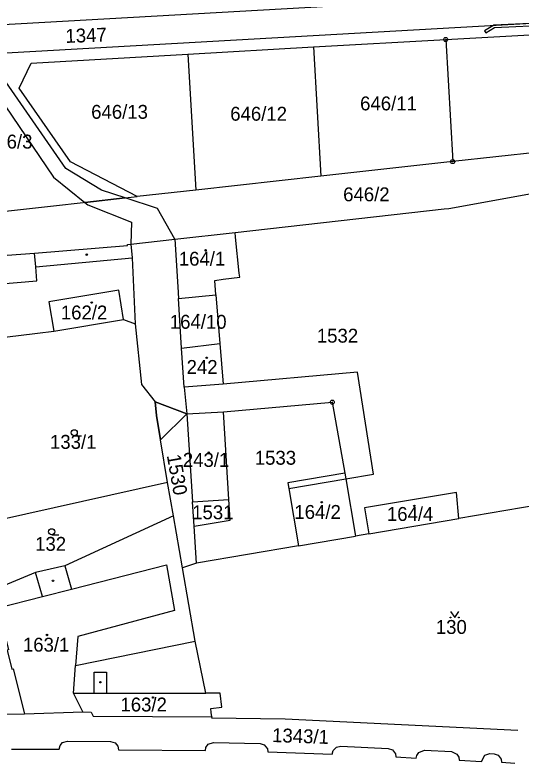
# Model space of a CAD drawing. Extents: x -537341 to -532984, y -1143469 to -1141314.
# Drawn here: x -533659.4 to -533535.5, y -1143096.3 to -1142913.3 of the extents above; entities that cross this region are included whole.
import ezdxf

# ---------------------------------------------------------------- set-up
doc = ezdxf.new("R2010")
doc.units = 0
for name, color, linetype in [('Hranice parcel', 7, 'Continuous'), ('parcelní_č_2000', 7, 'Continuous'), ('Vnitřní kresba', 7, 'Continuous'), ('Věcná břemena k části', 7, 'Continuous'), ('Značky bodu BP', 7, 'Continuous'), ('Značky budov', 7, 'Continuous'), ('Značky kultur', 7, 'Continuous')]:
    doc.layers.add(name, color=color, linetype=linetype)

msp = doc.modelspace()

# ---------------------------------------------------------------- linework, layer by layer
at = {"layer": 'Hranice parcel'}
for p, q in [((-533666.46, -1142915.84), (-533560.9, -1142909.85)), ((-533586.32, -1142921.09), (-533553.91, -1142919.27)), ((-533553.91, -1142919.27), (-533552.21, -1142949.14)), ((-533617.08, -1142922.83), (-533586.32, -1142921.09)), ((-533586.32, -1142921.09), (-533584.51, -1142952.72)), ((-533617.08, -1142922.83), (-533615.15, -1142956.13)), ((-533524.03, -1142946.01), (-533552.21, -1142949.14)), ((-533552.21, -1142949.14), (-533584.51, -1142952.72)), ((-533584.51, -1142952.72), (-533615.15, -1142956.13)), ((-533615.15, -1142956.13), (-533629.48, -1142957.72)), ((-533663.27, -1142961.47), (-533629.48, -1142957.72)), ((-533620.27, -1142968.15), (-533605.47, -1142966.49)), ((-533605.4, -1142967.65), (-533605.47, -1142966.49)), ((-533631.01, -1142969.31), (-533620.27, -1142968.15)), ((-533619.37, -1142982.64), (-533610.2, -1142981.72)), ((-533610.2, -1142981.72), (-533609.24, -1142993.64)), ((-533618.62, -1142994.79), (-533619.37, -1142982.64)), ((-533618.62, -1142994.79), (-533609.24, -1142993.64)), ((-533625.09, -1143007.91), (-533617.32, -1143010.84)), ((-533617.32, -1143010.84), (-533608.34, -1143010.37)), ((-533617.32, -1143010.84), (-533615.91, -1143032.37)), ((-533607.06, -1143031.82), (-533608.34, -1143010.37)), ((-533622.05, -1143027.66), (-533675.98, -1143039.7)), ((-533620.62, -1143035.85), (-533622.05, -1143027.66)), ((-533615.91, -1143032.37), (-533607.06, -1143031.82)), ((-533615.52, -1143038.34), (-533615.91, -1143032.37)), ((-533618.42, -1143048.52), (-533620.62, -1143035.85)), ((-533572.72, -1143040.23), (-533550.7, -1143036.5)), ((-533614.93, -1143047.39), (-533615.52, -1143038.34)), ((-533589.98, -1143043.16), (-533576.01, -1143040.79)), ((-533572.72, -1143040.23), (-533576.01, -1143040.79)), ((-533589.98, -1143043.16), (-533614.93, -1143047.39)), ((-533614.93, -1143047.39), (-533618.42, -1143048.52)), ((-533615.28, -1143066.53), (-533618.42, -1143048.52)), ((-533668.44, -1143084.49), (-533657.13, -1143084.25)), ((-533657.13, -1143084.25), (-533642.84, -1143083.81))]:
    msp.add_line(p, q, dxfattribs=at)
for points in [[(-533521.33, -1142914.7), (-533670.28, -1142923.14)], [(-533553.91, -1142919.27), (-533521.57, -1142917.45)], [(-533629.48, -1142957.72), (-533645.85, -1142949.18), (-533658.42, -1142931.2), (-533655.43, -1142925.03), (-533617.08, -1142922.83)], [(-533605.47, -1142966.49), (-533554.28, -1142960.73), (-533553.19, -1142960.59), (-533524.84, -1142955.48)], [(-533604.37, -1142977.44), (-533604.54, -1142976.41), (-533605.4, -1142967.65)], [(-533661.32, -1142972.07), (-533654.63, -1142971.54), (-533631.89, -1142969.71), (-533631.9, -1142969.41), (-533631.01, -1142969.31)], [(-533631.01, -1142969.31), (-533630.69, -1142972.7), (-533629.95, -1142988.83)], [(-533620.27, -1142968.15), (-533619.55, -1142979.78), (-533619.37, -1142982.64)], [(-533610.2, -1142981.72), (-533610.48, -1142978.27), (-533608.4, -1142977.92), (-533604.37, -1142977.44)], [(-533673.99, -1142993.57), (-533649.93, -1142990.6), (-533632.85, -1142987.8), (-533629.95, -1142988.83)], [(-533629.95, -1142988.83), (-533628.4, -1143003.7), (-533625.09, -1143007.91)], [(-533609.24, -1142993.64), (-533608.43, -1143003.59), (-533617.99, -1143004.35), (-533618.62, -1142994.79)], [(-533622.05, -1143027.66), (-533623.8, -1143017.22), (-533624.79, -1143011.27), (-533625.09, -1143007.91)], [(-533608.34, -1143010.37), (-533581.71, -1143008.01), (-533578.62, -1143025.41)], [(-533578.62, -1143025.41), (-533592.59, -1143027.78), (-533592.36, -1143029.15), (-533589.98, -1143043.16)], [(-533578.62, -1143025.41), (-533578.38, -1143026.79), (-533576.01, -1143040.79)], [(-533615.52, -1143038.34), (-533606.75, -1143036.87), (-533607.06, -1143031.82)], [(-533550.7, -1143036.5), (-533551.28, -1143030.12), (-533573.78, -1143033.88), (-533572.72, -1143040.23)], [(-533531.53, -1143033.25), (-533550.7, -1143036.5)], [(-533620.62, -1143035.85), (-533647.23, -1143048.1), (-533654.4, -1143049.71), (-533672.54, -1143057.19)], [(-533671.93, -1143060.22), (-533663.59, -1143058.34), (-533661.02, -1143068.63), (-533661.31, -1143068.71), (-533660.16, -1143073.31), (-533659.87, -1143073.24), (-533657.13, -1143084.25)], [(-533642.84, -1143083.81), (-533645.07, -1143079.19), (-533644.58, -1143072.41), (-533615.28, -1143066.53)], [(-533611.24, -1143085.02), (-533611.36, -1143083.92), (-533611.47, -1143082.94), (-533608.74, -1143082.67), (-533609.2, -1143079.21), (-533612.71, -1143079.21), (-533615.28, -1143066.53)], [(-533642.84, -1143083.81), (-533640.77, -1143083.9), (-533640.25, -1143084.88), (-533611.24, -1143085.02)], [(-533611.24, -1143085.02), (-533611.26, -1143085.26), (-533593.23, -1143085.48), (-533536.27, -1143088.29)], [(-533660.26, -1143092.92), (-533648.59, -1143092.9), (-533648.37, -1143092.01), (-533647.76, -1143091.31), (-533646.58, -1143090.93), (-533636, -1143091.02), (-533634.9, -1143091.39), (-533634.25, -1143092.15), (-533634.06, -1143093.07), (-533612.76, -1143093.28), (-533612.68, -1143092.51), (-533612.07, -1143091.7), (-533610.83, -1143091.28), (-533599.41, -1143091.54), (-533598.36, -1143091.83), (-533597.61, -1143092.85), (-533597.51, -1143093.61), (-533581.72, -1143094.12), (-533581.47, -1143093.23), (-533580.66, -1143092.43), (-533579.64, -1143092.2), (-533568.04, -1143092.72), (-533566.95, -1143093.11), (-533566.24, -1143094.04), (-533566.12, -1143094.82), (-533561.13, -1143095.1), (-533561, -1143094.44), (-533560.49, -1143093.7), (-533559.08, -1143093.18), (-533552.54, -1143093.52), (-533551.16, -1143094.18), (-533550.75, -1143094.84), (-533550.65, -1143095.63), (-533545.14, -1143095.91), (-533544.35, -1143094.38), (-533543.15, -1143094.01), (-533542.09, -1143094.06), (-533541.05, -1143094.43), (-533540.32, -1143095.39), (-533540.23, -1143096.14), (-533536.96, -1143096.32)]]:
    msp.add_lwpolyline(points, dxfattribs=at)
at = {"layer": 'Vnitřní kresba'}
for p, q in [((-533654.33, -1142974.86), (-533654.63, -1142971.54)), ((-533654.33, -1142974.86), (-533630.69, -1142972.7)), ((-533654.03, -1142978.3), (-533654.33, -1142974.86)), ((-533666.32, -1142979.34), (-533654.03, -1142978.3)), ((-533633.95, -1142980.6), (-533651.12, -1142983.46)), ((-533632.85, -1142987.8), (-533633.95, -1142980.6)), ((-533651.12, -1142983.46), (-533649.93, -1142990.6)), ((-533592.36, -1143029.15), (-533578.38, -1143026.79)), ((-533647.23, -1143048.1), (-533645.62, -1143053.76)), ((-533645.62, -1143053.76), (-533622.35, -1143047.83)), ((-533622.35, -1143047.83), (-533620.32, -1143059.03)), ((-533652.69, -1143055.56), (-533654.4, -1143049.71)), ((-533652.69, -1143055.56), (-533645.62, -1143053.76)), ((-533663.59, -1143058.34), (-533652.69, -1143055.56)), ((-533620.32, -1143059.03), (-533644.06, -1143065.33)), ((-533644.06, -1143065.33), (-533644.58, -1143072.41)), ((-533640.02, -1143079.2), (-533640.02, -1143074.11)), ((-533640.02, -1143074.11), (-533637.02, -1143074.11)), ((-533637.02, -1143074.11), (-533637.02, -1143079.2)), ((-533645.07, -1143079.19), (-533640.02, -1143079.2)), ((-533640.02, -1143079.2), (-533637.02, -1143079.2)), ((-533637.02, -1143079.2), (-533612.71, -1143079.21))]:
    msp.add_line(p, q, dxfattribs=at)
at = {"layer": 'Věcná břemena k části'}
msp.add_lwpolyline([(-533521.33, -1142914.66), (-533528.05, -1142915.1), (-533542.13, -1142915.74), (-533542.38, -1142915.89), (-533544.44, -1142917.16), (-533544.13, -1142917.67), (-533541.95, -1142916.34), (-533528.01, -1142915.7), (-533521.38, -1142915.27)], dxfattribs=at)
for points in [[(-533642.29, -1142959.14), (-533632.47, -1142958.05), (-533638.27, -1142956.15), (-533647, -1142950.83), (-533666.12, -1142923.25), (-533666.35, -1142922.92), (-533670.28, -1142923.14), (-533650, -1142952.97)], [(-533632.47, -1142958.05), (-533642.29, -1142959.14), (-533641.59, -1142959.7), (-533630.87, -1142963.98), (-533631.01, -1142969.31), (-533620.27, -1142968.15), (-533624.5, -1142960.66)], [(-533617.32, -1143010.84), (-533608.34, -1143010.37), (-533581.71, -1143008.01), (-533578.62, -1143025.41), (-533578.38, -1143026.79), (-533571.58, -1143025.64), (-533575.56, -1143000.68), (-533608.43, -1143003.59), (-533617.99, -1143004.35)], [(-533625.09, -1143007.91), (-533624.79, -1143011.27), (-533623.8, -1143017.22), (-533617.32, -1143010.84)]]:
    msp.add_lwpolyline(points, close=True, dxfattribs=at)
at = {"layer": 'Značky bodu BP'}
for centre, radius in [((-533553.91, -1142919.27), 0.5), ((-533553.91, -1142919.27), 0.0303), ((-533552.21, -1142949.14), 0.5), ((-533552.21, -1142949.14), 0.0303), ((-533581.71, -1143008.01), 0.5), ((-533581.71, -1143008.01), 0.0303)]:
    msp.add_circle(centre, radius, dxfattribs=at)
at = {"layer": 'Značky budov'}
for centre in [(-533612.75, -1142970.85), (-533641.83, -1142971.91), (-533640.63, -1142983.64), (-533614.56, -1142986.65), (-533612.44, -1142997.14), (-533611.96, -1143020.35), (-533584.29, -1143032.51), (-533561.6, -1143033.39), (-533650.1, -1143051.71), (-533651.59, -1143064.98), (-533638.5, -1143076.53), (-533625.59, -1143080.28)]:
    msp.add_circle(centre, 0.175, dxfattribs=at)
at = {"layer": 'Značky kultur'}
for p, q in [((-533644.92, -1143016.26), (-533643.17, -1143016.26)), ((-533650.43, -1143040.48), (-533648.68, -1143040.48))]:
    msp.add_line(p, q, dxfattribs=at)
msp.add_lwpolyline([(-533552.73, -1143059.21), (-533551.73, -1143060.71), (-533550.73, -1143059.21)], dxfattribs=at)
for centre, radius in [((-533644.92, -1143015.51), 0.75), ((-533650.43, -1143039.73), 0.75), ((-533552.73, -1143060.71), 0.1), ((-533550.73, -1143060.71), 0.1)]:
    msp.add_circle(centre, radius, dxfattribs=at)

# ---------------------------------------------------------------- texts
at = {"layer": 'parcelní_č_2000'}
for s, rotation, p in [('1347', 2, (-533647.01, -1142920.12)), ('1530', 280, (-533622.25, -1143021.06)), ('1343/1', 358, (-533596.49, -1143091.17))]:
    msp.add_text(s, height=3.4, rotation=rotation, dxfattribs=at).set_placement(p)
for s, p in [('646/11', (-533574.89, -1142936.61)), ('646/13', (-533640.76, -1142938.67)), ('646/12', (-533606.7, -1142939.14)), ('646/3', (-533666.52, -1142945.95)), ('646/2', (-533579.04, -1142958.86)), ('164/1', (-533619.3, -1142974.61)), ('162/2', (-533648.19, -1142987.77)), ('164/10', (-533621.5, -1142990.05)), ('1532', (-533585.49, -1142993.45)), ('242', (-533617.38, -1143001.1)), ('133/1', (-533650.84, -1143019.43)), ('243/1', (-533618.31, -1143023.84)), ('1533', (-533600.69, -1143023.32)), ('1531', (-533616.02, -1143036.66)), ('164/2', (-533590.99, -1143036.58)), ('164/4', (-533568.33, -1143037.07)), ('132', (-533654.49, -1143044.39)), ('130', (-533556.35, -1143064.72)), ('163/1', (-533657.48, -1143069.06)), ('163/2', (-533633.59, -1143083.7))]:
    msp.add_text(s, height=3.4, dxfattribs=at).set_placement(p)

doc.saveas('drawing.dxf')
